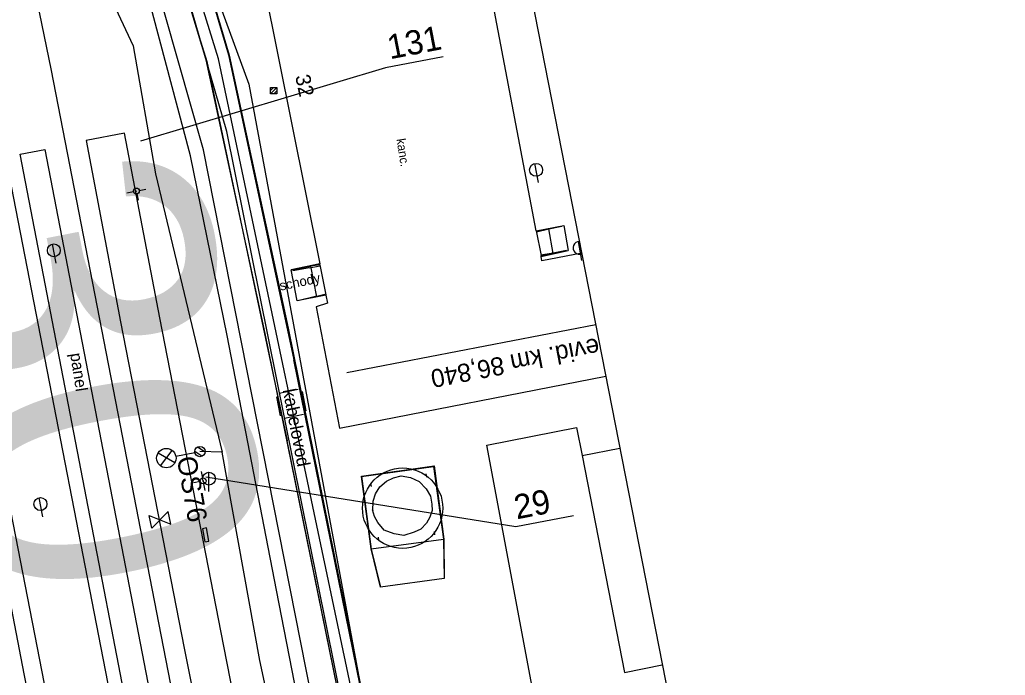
# Model space of a CAD drawing. Extents: x -545736 to -544888, y -1122892 to -1119128.
# Drawn here: x -545139.7 to -545063.6, y -1121801.4 to -1121750.7 of the extents above; entities that cross this region are included whole.
import ezdxf

# ---------------------------------------------------------------- set-up
doc = ezdxf.new("R2010")
doc.units = 0
for name, color, linetype in [('osvětlené plochy-hodnota-obrys', 7, 'Continuous'), ('so180602', 7, 'Continuous'), ('Vrstva 1', 7, 'Continuous'), ('Vrstva 10', 7, 'Continuous'), ('Vrstva 11', 7, 'Continuous'), ('Vrstva 12', 7, 'Continuous'), ('Vrstva 16', 7, 'Continuous'), ('Vrstva 17', 7, 'Continuous'), ('Vrstva 18_mosty', 7, 'Continuous'), ('Vrstva 21', 7, 'Continuous'), ('Vrstva 23', 7, 'Continuous'), ('Vrstva 25', 7, 'Continuous'), ('Vrstva 26', 7, 'Continuous'), ('Vrstva 34', 7, 'Continuous'), ('Vrstva 35', 7, 'Continuous'), ('Vrstva 36', 7, 'Continuous'), ('Vrstva 41', 7, 'Continuous'), ('Vrstva 43', 7, 'Continuous'), ('Vrstva 49', 7, 'Continuous'), ('Vrstva 63', 7, 'Continuous')]:
    doc.layers.add(name, color=color, linetype=linetype)

msp = doc.modelspace()

# ---------------------------------------------------------------- linework, layer by layer
at = {"layer": 'osvětlené plochy-hodnota-obrys'}
msp.add_lwpolyline([(-545114.36, -1122142.005), (-545095.834, -1122030.811), (-545094.039, -1122008.497), (-545094.672, -1121983.393), (-545097.737, -1121961.902), (-545099.42, -1121918.553), (-545101.285, -1121870.536), (-545123.71, -1121759.379), (-545130.296, -1121736.567), (-545147.419, -1121693.847), (-545162.352, -1121662.092), (-545176.655, -1121642.604), (-545199.404, -1121614.631), (-545212.209, -1121594.037), (-545225.557, -1121565.516)], dxfattribs=at)
at = {"layer": 'Vrstva 1'}
for points in [[(-545136.138, -1121810.482), (-545151.439, -1121732.001), (-545153.811, -1121720.884), (-545157.079, -1121707.235), (-545158.713, -1121700.975), (-545160.827, -1121693.838), (-545161.595, -1121691.453), (-545162.959, -1121687.383)], [(-545122.391, -1121831.073), (-545137.243, -1121754.649), (-545140.565, -1121738.508), (-545144.406, -1121723.735)], [(-545129.964, -1121816.995), (-545141.92, -1121755.645), (-545147.356, -1121729.026)], [(-545112.214, -1121833.922), (-545112.391, -1121833.027), (-545112.889, -1121830.494), (-545116.087, -1121814.177), (-545119.882, -1121794.779), (-545123.693, -1121775.109), (-545126.522, -1121761.24), (-545129.884, -1121748.545), (-545134.913, -1121734.467)]]:
    msp.add_lwpolyline(points, dxfattribs=at)
at = {"layer": 'Vrstva 10'}
msp.add_line((-545169.988, -1121392.291), (-544887.573, -1122835.274), dxfattribs=at)
at = {"layer": 'Vrstva 11'}
for p, q in [((-545120.105, -1121755.968), (-545120.341, -1121756.204)), ((-545119.841, -1121755.97), (-545120.34, -1121756.468)), ((-545119.841, -1121756.235), (-545120.074, -1121756.468))]:
    msp.add_line(p, q, dxfattribs=at)
msp.add_lwpolyline([(-545119.841, -1121756.468), (-545120.341, -1121756.468), (-545120.341, -1121755.968), (-545119.841, -1121755.968)], close=True, dxfattribs=at)
msp.add_lwpolyline([(-545119.841, -1121756.468), (-545120.341, -1121756.468), (-545120.341, -1121755.968), (-545119.841, -1121755.968), (-545119.841, -1121756.468)], dxfattribs=at)
at = {"layer": 'Vrstva 12'}
for p, q in [((-545107.742, -1121785.237), (-545107.709, -1121785.192)), ((-545113.314, -1121785.982), (-545112.578, -1121791.61)), ((-545113.302, -1121786.008), (-545113.314, -1121785.982)), ((-545112.562, -1121791.578), (-545106.975, -1121790.853)), ((-545106.975, -1121790.853), (-545106.957, -1121790.854)), ((-545106.957, -1121790.854), (-545106.918, -1121793.867)), ((-545112.562, -1121791.578), (-545112.578, -1121791.61)), ((-545112.578, -1121791.61), (-545111.832, -1121794.541))]:
    msp.add_line(p, q, dxfattribs=at)
msp.add_lwpolyline([(-545113.314, -1121785.982), (-545107.709, -1121785.192), (-545106.957, -1121790.854)], dxfattribs=at)
msp.add_lwpolyline([(-545113.302, -1121786.008), (-545107.742, -1121785.237), (-545106.975, -1121790.853), (-545106.918, -1121793.867), (-545111.832, -1121794.541), (-545112.562, -1121791.578)], close=True, dxfattribs=at)
at = {"layer": 'Vrstva 16'}
msp.add_line((-545139.677, -1121761.116), (-545137.763, -1121760.75), dxfattribs=at)
for points in [[(-545130.783, -1121729.098), (-545126.921, -1121742.28), (-545122.013, -1121755.705), (-545113.133, -1121803.552), (-545107.528, -1121836.133)], [(-545110.484, -1121836.846), (-545125.51, -1121760.796), (-545130.432, -1121743.48), (-545134.031, -1121732.322), (-545133.052, -1121729.861)], [(-545133.605, -1121828.686), (-545133.974, -1121828.704), (-545139.373, -1121801.248), (-545143.008, -1121782.331), (-545150.688, -1121743.03), (-545152.611, -1121743.365), (-545144.864, -1121782.981), (-545141.222, -1121801.572)], [(-545120.706, -1121815.657), (-545123.951, -1121799.11), (-545128.895, -1121773.755), (-545131.614, -1121759.507), (-545134.577, -1121760.055), (-545131.932, -1121774.061), (-545126.998, -1121799.269), (-545123.516, -1121816.78)], [(-545137.763, -1121760.75), (-545124.317, -1121830.316), (-545126.266, -1121830.665), (-545139.677, -1121761.116)]]:
    msp.add_lwpolyline(points, dxfattribs=at)
at = {"layer": 'Vrstva 17'}
for p, q in [((-545117.318, -1121769.894), (-545118.603, -1121770.135)), ((-545117.318, -1121769.894), (-545116.524, -1121769.739)), ((-545116.855, -1121772.099), (-545118.131, -1121772.429)), ((-545116.855, -1121772.099), (-545116.138, -1121771.935)), ((-545096.282, -1121784.377), (-545093.358, -1121783.827))]:
    msp.add_line(p, q, dxfattribs=at)
for points in [[(-545099.808, -1121767.117), (-545098.85, -1121766.895), (-545097.85, -1121766.681)], [(-545099.452, -1121768.897), (-545098.516, -1121768.731), (-545097.474, -1121768.523)]]:
    msp.add_lwpolyline(points, dxfattribs=at)
at = {"layer": 'Vrstva 18_mosty'}
msp.add_line((-545095.226, -1121774.283), (-545114.446, -1121777.998), dxfattribs=at)
at = {"layer": 'Vrstva 21'}
msp.add_lwpolyline([(-545128.041, -1121789.693), (-545128.241, -1121788.713), (-545129.511, -1121789.991), (-545129.711, -1121789.011), (-545128.041, -1121789.693)], dxfattribs=at)
at = {"layer": 'Vrstva 23'}
for p, q in [((-545099.824, -1121767.029), (-545097.688, -1121766.625)), ((-545099.814, -1121767.046), (-545099.448, -1121768.93)), ((-545098.876, -1121766.881), (-545098.535, -1121768.783)), ((-545097.688, -1121766.625), (-545097.357, -1121768.545)), ((-545099.437, -1121769.028), (-545097.357, -1121768.545)), ((-545116.524, -1121769.584), (-545118.734, -1121770.056)), ((-545116.518, -1121769.668), (-545116.524, -1121769.584))]:
    msp.add_line(p, q, dxfattribs=at)
for points in [[(-545115.751, -1121736.12), (-545116.453, -1121733.461), (-545124.368, -1121735.019), (-545121.77, -1121748.345), (-545120.837, -1121748.166), (-545116.524, -1121769.584)], [(-545099.824, -1121767.029), (-545104.13, -1121744.384), (-545107.52, -1121745.023), (-545107.642, -1121744.385), (-545115.825, -1121745.941), (-545116.544, -1121742.159), (-545113.057, -1121741.495), (-545114.201, -1121735.711), (-545115.751, -1121736.12)], [(-545099.824, -1121767.029), (-545099.814, -1121767.046), (-545098.876, -1121766.881), (-545097.688, -1121766.625)], [(-545099.437, -1121769.028), (-545099.448, -1121768.93), (-545098.535, -1121768.783), (-545097.357, -1121768.545)], [(-545096.307, -1121768.76), (-545099.382, -1121769.351), (-545099.437, -1121769.028)], [(-545116.518, -1121769.668), (-545117.243, -1121769.775), (-545116.778, -1121772.13), (-545118.282, -1121772.44), (-545118.734, -1121770.056), (-545117.243, -1121769.775)], [(-545116.518, -1121769.668), (-545116.065, -1121771.987), (-545116.778, -1121772.13)], [(-545116.065, -1121771.987), (-545116.06, -1121772.008), (-545118.282, -1121772.44)], [(-545116.06, -1121772.008), (-545115.935, -1121772.618), (-545116.823, -1121772.91), (-545115.02, -1121782.283), (-545094.45, -1121778.245)], [(-545104.636, -1121837.431), (-545099.791, -1121821.468), (-545102.892, -1121804.54), (-545099.811, -1121803.899), (-545103.633, -1121783.576), (-545096.713, -1121782.22)], [(-545096.713, -1121782.22), (-545096.282, -1121784.377)], [(-545096.282, -1121784.377), (-545092.999, -1121801.129), (-545090.088, -1121800.534)]]:
    msp.add_lwpolyline(points, dxfattribs=at)
msp.add_lwpolyline([(-545112.443, -1121788.651), (-545112.406, -1121787.908), (-545112.23, -1121787.338), (-545111.906, -1121786.79), (-545111.389, -1121786.359), (-545110.828, -1121786.114), (-545110.241, -1121785.961), (-545109.515, -1121786.073), (-545108.846, -1121786.385), (-545108.326, -1121786.955), (-545107.985, -1121787.51), (-545107.87, -1121788.131), (-545107.851, -1121788.641), (-545108.04, -1121789.148), (-545108.301, -1121789.618), (-545108.729, -1121790.07), (-545109.252, -1121790.314), (-545110.042, -1121790.554), (-545110.802, -1121790.436), (-545111.562, -1121790.156), (-545112.06, -1121789.568), (-545112.306, -1121789.098), (-545112.466, -1121788.571)], close=True, dxfattribs=at)
at = {"layer": 'Vrstva 25'}
for p, q in [((-545128.838, -1121785.173), (-545127.937, -1121783.985)), ((-545125.632, -1121784.442), (-545126.182, -1121784.071)), ((-545125.392, -1121784.122), (-545125.978, -1121783.727)), ((-545127.732, -1121784.943), (-545129.021, -1121784.191)), ((-545127.65, -1121784.439), (-545126.178, -1121784.152))]:
    msp.add_line(p, q, dxfattribs=at)
for centre, radius in [((-545128.384, -1121784.585), 0.749), ((-545125.785, -1121784.075), 0.4), ((-545125.785, -1121784.075), 0.4)]:
    msp.add_circle(centre, radius, dxfattribs=at)
at = {"layer": 'Vrstva 26'}
for points in [[(-545097.437, -1122052.623), (-545072.287, -1122039.894), (-545085.621, -1122009.744), (-545089.841, -1121964.946), (-545095.239, -1121958.274), (-545095.745, -1121940.272), (-545098.424, -1121935.947), (-545099.088, -1121910.293), (-545099.581, -1121891.247), (-545095.82, -1121860.673), (-545104.239, -1121857.434), (-545113.591, -1121811.167), (-545113.924, -1121803.223), (-545124.359, -1121753.762), (-545132.104, -1121728.782), (-545141.308, -1121704.806), (-545150.282, -1121669.65), (-545151.919, -1121656.143), (-545151.404, -1121636.531), (-545180.167, -1121637.447), (-545212.798, -1121581.796), (-545235.977, -1121514.184), (-545242.54, -1121484.599), (-545257.211, -1121409.362)], [(-545129.421, -1121742.586), (-545135.013, -1121744.055), (-545130.954, -1121752.75), (-545129.213, -1121762.627), (-545124.063, -1121784.124)], [(-545111.712, -1121858.477), (-545109.668, -1121857.569), (-545112.9, -1121839.62), (-545112.626, -1121838.172), (-545113.115, -1121836.08), (-545113.96, -1121833.409), (-545116.212, -1121821.755), (-545116.359, -1121819.204), (-545117.683, -1121812.861), (-545118.163, -1121810.398), (-545118.986, -1121810.372), (-545121.163, -1121800.213), (-545124.063, -1121784.124), (-545125.785, -1121784.075)]]:
    msp.add_lwpolyline(points, dxfattribs=at)
at = {"layer": 'Vrstva 34'}
for p, q in [((-545119.668, -1121779.565), (-545118.199, -1121779.259)), ((-545117.904, -1121779.453), (-545117.598, -1121780.922)), ((-545119.556, -1121781.329), (-545119.862, -1121779.86)), ((-545117.792, -1121781.217), (-545119.261, -1121781.523))]:
    msp.add_line(p, q, dxfattribs=at)
at = {"layer": 'Vrstva 35'}
msp.add_lwpolyline([(-545104.086, -1121853.427), (-545105.839, -1121853.763), (-545110.578, -1121830.258), (-545114.351, -1121811.394), (-545114.89, -1121803.777), (-545120.74, -1121774.952), (-545125.306, -1121753.837), (-545126.379, -1121750.254), (-545132.738, -1121729.703), (-545130.974, -1121729.174), (-545124.65, -1121749.755), (-545123.527, -1121753.488), (-545118.979, -1121774.543), (-545113.13, -1121803.368), (-545112.576, -1121810.999), (-545108.803, -1121829.91)], close=True, dxfattribs=at)
at = {"layer": 'Vrstva 36'}
for p, q in [((-545108.335, -1121785.808), (-545108.301, -1121786.055)), ((-545112.607, -1121786.534), (-545112.573, -1121786.781)), ((-545112.032, -1121790.682), (-545112, -1121790.929)), ((-545107.704, -1121790.25), (-545107.672, -1121790.497))]:
    msp.add_line(p, q, dxfattribs=at)
msp.add_lwpolyline([(-545125.419, -1121791.05), (-545125.092, -1121790.996), (-545125.285, -1121789.955), (-545125.595, -1121790.04)], close=True, dxfattribs=at)
msp.add_ellipse((-545110.133, -1121788.448), major_axis=(0, 3.102), ratio=0.999507, dxfattribs=at)
at = {"layer": 'Vrstva 41'}
for p, q in [((-545131.434, -1121764.103), (-545130.918, -1121764.004)), ((-545130.722, -1121763.967), (-545130.672, -1121763.957)), ((-545130.655, -1121764.183), (-545130.561, -1121764.674)), ((-545130.476, -1121763.92), (-545129.96, -1121763.821)), ((-545125.688, -1121785.607), (-545125.587, -1121786.122)), ((-545125.549, -1121786.318), (-545125.539, -1121786.368)), ((-545125.765, -1121786.386), (-545126.256, -1121786.482)), ((-545125.501, -1121786.564), (-545125.4, -1121787.079))]:
    msp.add_line(p, q, dxfattribs=at)
for centre in [(-545130.697, -1121763.962), (-545125.544, -1121786.343)]:
    msp.add_circle(centre, 0.225, dxfattribs=at)
at = {"layer": 'Vrstva 43'}
for p, q in [((-545099.64, -1121763.314), (-545099.92, -1121761.843)), ((-545136.879, -1121769.526), (-545137.169, -1121768.056)), ((-545096.3, -1121769.334), (-545096.555, -1121767.858)), ((-545125.092, -1121787.169), (-545125.092, -1121785.671)), ((-545137.915, -1121789.115), (-545138.201, -1121787.644))]:
    msp.add_line(p, q, dxfattribs=at)
for centre in [(-545099.827, -1121762.332), (-545137.072, -1121768.545), (-545125.092, -1121786.169), (-545138.106, -1121788.133)]:
    msp.add_circle(centre, 0.498, dxfattribs=at)
msp.add_arc((-545096.47, -1121768.349), 0.498, 91.68759, 290.45981, dxfattribs=at)
at = {"layer": 'Vrstva 49'}
for points in [[(-545126.482, -1121743.586), (-545123.577, -1121753.447), (-545118.542, -1121777.008)], [(-545126.789, -1121748.961), (-545125.265, -1121753.962), (-545119.056, -1121783.258)], [(-545104.002, -1121853.864), (-545112.614, -1121810.989), (-545113.095, -1121803.664), (-545118.542, -1121777.008)], [(-545105.733, -1121854.262), (-545114.375, -1121811.186), (-545114.86, -1121803.892), (-545119.056, -1121783.258)]]:
    msp.add_lwpolyline(points, dxfattribs=at)
at = {"layer": 'Vrstva 63'}
for p, q in [((-545107.005, -1121753.599), (-545111.45, -1121754.464)), ((-545111.45, -1121754.464), (-545130.385, -1121760.115)), ((-545101.392, -1121789.899), (-545125.341, -1121786.048)), ((-545096.947, -1121789.035), (-545101.392, -1121789.899))]:
    msp.add_line(p, q, dxfattribs=at)

# ---------------------------------------------------------------- texts
at = {"layer": 'osvětlené plochy-hodnota-obrys'}
msp.add_text('30', height=22.7812, rotation=281.09556, dxfattribs=at).set_placement((-545148.957, -1121763.514))
at = {"layer": 'so180602'}
for s, p in [('131', (-545111.122, -1121753.801)), ('29', (-545101.331, -1121789.319))]:
    msp.add_text(s, height=1.875, rotation=10.99553, dxfattribs=at).set_placement(p)
at = {"layer": 'Vrstva 11'}
msp.add_text('32', height=1.1507, rotation=282.33967, dxfattribs=at).set_placement((-545118.442, -1121755.101))
at = {"layer": 'Vrstva 16'}
for s, height, rotation, p in [('panel', 0.915, 278.74018, (-545135.813, -1121776.528)), ('kabelovod', 1, 280.91164, (-545119.403, -1121779.331))]:
    msp.add_text(s, height=height, rotation=rotation, dxfattribs=at).set_placement(p)
at = {"layer": 'Vrstva 18_mosty'}
msp.add_text('evid. km 86,840', height=1.4, rotation=190.93735, dxfattribs=at).set_placement((-545095.083, -1121775.293))
at = {"layer": 'Vrstva 23'}
for s, height, rotation, p in [('kanc.', 0.6863, 278.81824, (-545110.615, -1121759.961)), ('schody', 0.75, 11.64653, (-545119.561, -1121771.659))]:
    msp.add_text(s, height=height, rotation=rotation, dxfattribs=at).set_placement(p)
at = {"layer": 'Vrstva 25'}
msp.add_text('OS76', height=1.5, rotation=280.2177, dxfattribs=at).set_placement((-545127.581, -1121784.58))

doc.saveas('drawing.dxf')
